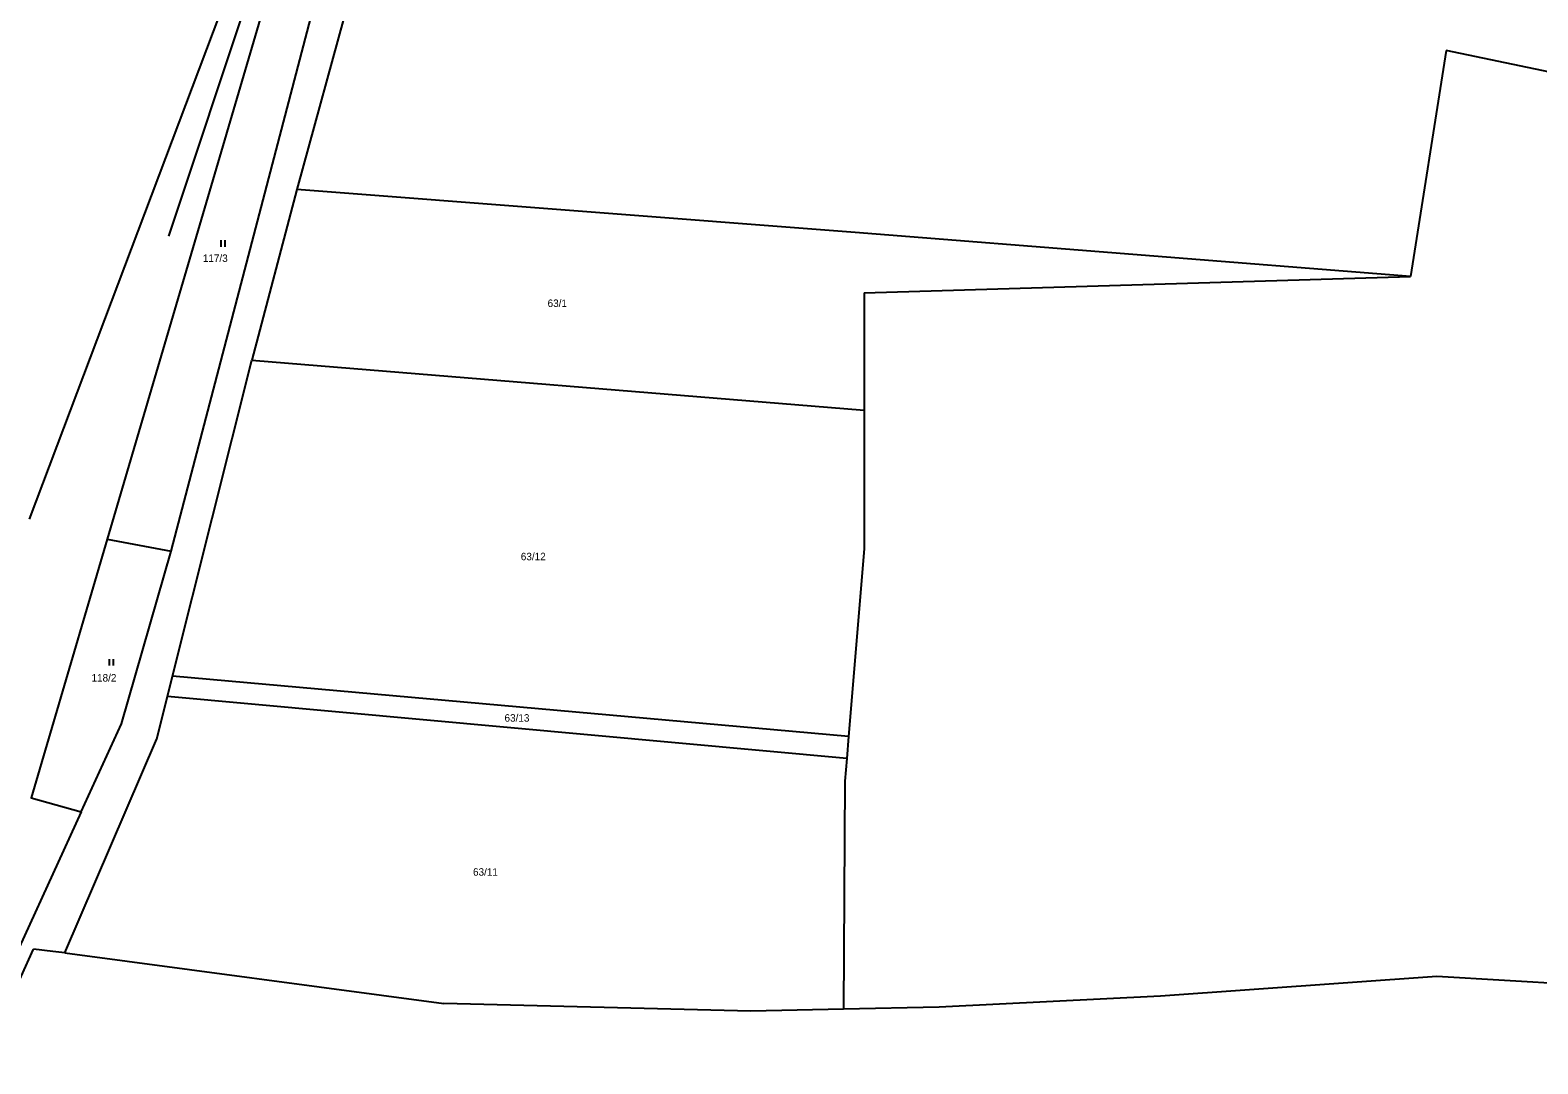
# Model space of a CAD drawing. Extents: x -752343 to -750336, y -1035826 to -1033329.
# Drawn here: x -752019.3 to -751675.2, y -1035482.2 to -1035246.4 of the extents above; entities that cross this region are included whole.
import ezdxf

# ---------------------------------------------------------------- set-up
doc = ezdxf.new("R2010")
doc.units = 0
for name, color, linetype in [('Default', 7, 'Continuous'), ('KN_HRANICE', 7, 'Continuous'), ('KN_KULTURY', 7, 'Continuous'), ('KN_PARCELY', 7, 'Continuous'), ('Vrstva 1', 7, 'Continuous')]:
    doc.layers.add(name, color=color, linetype=linetype)

# ---------------------------------------------------------------- blocks, each defined once
blk = doc.blocks.new('306')
at = {"layer": 'Default'}
for p, q in [((-0.5, 1.5), (-0.5, 0)), ((0.5, 0), (0.5, 1.5))]:
    blk.add_line(p, q, dxfattribs=at)

msp = doc.modelspace()

# ---------------------------------------------------------------- linework, layer by layer
at = {"layer": 'KN_HRANICE'}
for p, q in [((-751972.29, -1035232.78), (-752019.52, -1035357.91)), ((-751963.67, -1035233.09), (-752001.66, -1035362.46)), ((-751987.07, -1035365.19), (-751953.14, -1035235.55)), ((-751944.7, -1035232.59), (-751958.36, -1035282.73)), ((-751696.06, -1035251.03), (-751704.26, -1035302.52)), ((-751628.48, -1035265.07), (-751696.06, -1035251.03)), ((-751958.36, -1035282.73), (-751968.67, -1035321.63)), ((-751830.96, -1035292.49), (-751958.36, -1035282.73)), ((-751704.26, -1035302.52), (-751830.96, -1035292.49)), ((-751828.91, -1035306.31), (-751704.26, -1035302.52)), ((-751828.91, -1035306.31), (-751828.91, -1035333.06)), ((-751986.77, -1035393.76), (-751968.67, -1035321.63)), ((-751968.67, -1035321.63), (-751828.91, -1035333.06)), ((-751828.91, -1035333.06), (-751828.91, -1035364.7)), ((-752001.66, -1035362.46), (-751987.07, -1035365.19)), ((-751828.91, -1035364.7), (-751832.47, -1035407.49)), ((-751987.93, -1035398.4), (-751986.77, -1035393.76)), ((-751832.47, -1035407.49), (-751986.77, -1035393.76)), ((-751990.35, -1035408.04), (-751987.93, -1035398.4)), ((-751832.89, -1035412.54), (-751987.93, -1035398.4)), ((-751832.47, -1035407.49), (-751832.89, -1035412.54)), ((-752011.32, -1035456.85), (-751990.35, -1035408.04)), ((-751832.89, -1035412.54), (-751833.32, -1035417.65)), ((-751833.32, -1035417.65), (-751833.64, -1035469.7)), ((-752007.58, -1035424.66), (-752033.74, -1035481.68)), ((-752030.48, -1035482.16), (-752018.47, -1035455.97)), ((-752014.06, -1035456.51), (-752018.47, -1035455.97)), ((-752011.32, -1035456.85), (-752014.06, -1035456.51)), ((-752011.32, -1035456.85), (-751924.86, -1035468.38)), ((-751698.2, -1035462.25), (-751761.3, -1035466.73)), ((-751661.64, -1035464.37), (-751698.2, -1035462.25)), ((-751854.78, -1035470.18), (-751924.86, -1035468.38)), ((-751811.82, -1035469.21), (-751833.64, -1035469.7)), ((-751761.3, -1035466.73), (-751811.82, -1035469.21)), ((-751833.64, -1035469.7), (-751854.78, -1035470.18))]:
    msp.add_line(p, q, dxfattribs=at)
for points in [[(-752001.66, -1035362.46), (-752019, -1035421.5), (-752007.58, -1035424.66)], [(-752007.58, -1035424.66), (-751998.38, -1035404.62), (-751987.07, -1035365.19)]]:
    msp.add_lwpolyline(points, dxfattribs=at)
at = {"layer": 'Vrstva 1'}
msp.add_lwpolyline([(-751987.62, -1035293.38), (-751985.33, -1035286.49), (-751971.34, -1035244.47), (-751966.7, -1035230.47), (-751964.62, -1035224.16), (-751953.68, -1035191.34), (-751941.61, -1035155.08), (-751927.04, -1035111.3), (-751924.06, -1035102.35), (-751922.14, -1035096.59), (-751909.33, -1035058.09), (-751906.33, -1035049.09), (-751897.2, -1035021.76), (-751890.47, -1035001.59)], dxfattribs=at)

# ---------------------------------------------------------------- block references
at = {"layer": 'KN_KULTURY'}
for p in [(-751975.26, -1035295.78), (-752000.73, -1035391.31)]:
    msp.add_blockref('306', p, dxfattribs=at)

# ---------------------------------------------------------------- texts
at = {"layer": 'KN_PARCELY'}
for s, p in [('117/3', (-751979.86, -1035299.23)), ('63/1', (-751901.17, -1035309.5)), ('63/12', (-751907.28, -1035367.28)), ('118/2', (-752005.26, -1035394.95)), ('63/13', (-751911, -1035404.1)), ('63/11', (-751918.19, -1035439.24))]:
    msp.add_text(s, height=1.7, dxfattribs=at).set_placement(p)

doc.saveas('drawing.dxf')
